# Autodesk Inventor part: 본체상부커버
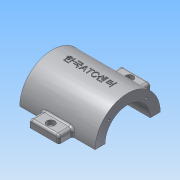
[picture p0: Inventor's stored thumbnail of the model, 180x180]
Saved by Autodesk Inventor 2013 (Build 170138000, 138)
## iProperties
Created: 2015-12
Part Number: 본체상부커버
Material: 알루미늄 6061
Document SubType Name: Modeling
Designer: mduedu
Density: 2.71 g/cm^3
Mass: 190.123 g
Surface Area: 187.8 cm^2
Volume: 70.1561 cm^3
Author: mduedu
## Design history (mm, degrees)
sketch "스케치1"
  geometry: L1 (45, 40)-(-45, 40); L2 (-45, 40)-(-45, -40); L3 (-45, -40)-(45, -40); L4 (45, -40)-(45, 40); L5 (45, 40)-(-45, -40); L6 (-45, 40)-(45, -40); 2 further points
  constraints: 12 end point, 2 midpoint, 2 parallel, 1 coincident, 1 horizontal, 1 perpendicular, 3 other
  dimensions: "d0" = 90 distance of L2.end L3.end; "d2" = 80 distance of L1.end L2.end
extrude "돌출1" new body sketch "스케치1" distance "d3" = 10; taper "d4" = 0 deg
sketch "스케치2"
  geometry: C1 r 32.5 at (80, 0); 1 further point
  constraints: 1 centre point
  dimensions: "d5" = 65 diameter of C1; "d116" = 80 distance of point (0, 0) C1.centre
extrude "돌출2" join sketch "스케치2" stored distance "d7" = 75; taper "d8" = 0 deg
sketch "스케치3"
  geometry: L1 (-27.5, -20)-(27.5, -20); L2 (27.5, -20)-(27.5, 20); L3 (27.5, 20)-(-27.5, 20); L4 (-27.5, 20)-(-27.5, -20); L5 (-27.5, -20)-(27.5, 20); L6 (27.5, -20)-(-27.5, 20); 1 further point
  constraints: 12 end point, 2 midpoint, 2 parallel, 1 horizontal, 1 perpendicular
  dimensions: "d9" = 55 distance of L2.end L3.end; "d11" = 40 distance of L1.end L2.end
extrude "돌출3" new body sketch "스케치3" stored distance "d12" = 75; taper "d13" = 0 deg
fillet "모깎기1"
fillet "모깎기2"
feature "결합1"
  node "솔리드2"
sketch "스케치4"
  geometry: L1 (-37.5, 47.5)-(37.5, 47.5) reference; L2 (32.5, 47.5)-(40.208, 10); L3 (37.5, 47.5)-(37.5, 112.5) reference; L4 (60.208, 0)-(60.208, 10) reference; L5 (60.208, 10)-(-60.208, 10) reference; 1 further point
  constraints: 2 end point, 2 point on line
  dimensions: "d15" = 5 distance from line of L2.start L3; "d117" = 20 distance from line of L2.end L4
sketch "스케치5"
  geometry: L1 (10, 35.208)-(56.729, 22.687); L2 (0, 60.208)-(10, 60.208) reference; L3 (10, -60.208)-(10, 60.208) reference; 2 further points
  constraints: 2 end point, 1 point on line, 2 other
  dimensions: "d118" = 25 distance from line of L1.start L2; "d119" = 75 deg angle of L1 L3
feature "리브1" dims "d19" = 1, "d20" = 6, "d21" = 0, "d22" = 0, "d23" = 1, "d24" = 1
feature "리브2" dims "d25" = 1, "d26" = 6, "d27" = 0, "d28" = 0, "d29" = 1, "d30" = 1
fillet "모깎기4" dims "d31" = 2
fillet "모깎기5" dims "d32" = 2
fillet "모깎기6" dims "d33" = 2
sketch "스케치6"
  geometry: L1 (0, 0)-(-32.88, 32.88); L2 (0, 0)-(-46.5, 0); A1 r 46.5 centre (0, 0) between (-32.88, 32.88) and (-46.5, 0); 5 further points
  constraints: 4 end point, 2 coincident, 2 point on circle, 1 centre point, 1 horizontal, 5 other
  dimensions: "d120" = 93 diameter of A1; "d122" = 45 deg angle of L1 L2; "d126" = 360 deg dimension on point (0, 0) point (-32.88, 32.88) (derived)
hole "구멍1" sketch "스케치6" at (-32.88, 32.88), (-32.88, -32.88), (32.88, -32.88), (32.88, 32.88) diameter "d34" = 7; stored, may be unused: countersink angle "d38" = 90 deg, drill point angle "d40" = 118 deg; dims "d35" = 6, "d36" = 12, "d37" = 3, "d39" = 8
fillet "모깎기13" dims "d131" = 3
hole "구멍2" diameter "d44" = 45; stored, may be unused: countersink angle "d48" = 90 deg, drill point angle "d50" = 118 deg; dims "d42" = 10, "d43" = 10, "d45" = 6, "d46" = 4, "d47" = 2, "d49" = 8
sketch "스케치7" dims "d52" = 26.5
  geometry: L1 (0, 0)-(32.5, 0); L2 (0, 0)-(22.981, 22.981); A1 r 32.5 centre (0, 0) between (32.5, 0) and (22.981, 22.981) reference; 3 further points
  constraints: 4 end point, 2 point on circle, 1 coincident, 1 horizontal, 1 point on line, 3 other
  dimensions: "d51" = 45 deg angle of L2 L1
hole "구멍3" sketch "스케치7" at (18.738, 18.738) diameter "d54" = 2.459; stored, may be unused: countersink angle "d58" = 90 deg, drill point angle "d60" = 118 deg; dims "d55" = 8, "d56" = 4, "d57" = 2, "d59" = 10
sketch "스케치8"
  geometry: L1 (72.5, 31.623)-(72.5, 46); L2 (72.5, 46)-(87.5, 46); L3 (87.5, 46)-(87.5, 31.623); A1 r 32.5 centre (80, 0) between (87.5, 31.623) and (72.5, 31.623) reference; 2 further points
  constraints: 6 end point, 2 point on circle, 1 horizontal, 1 midpoint, 1 parallel, 1 vertical, 1 vertical alignment
  dimensions: "d64" = 15 distance of L1.end L2.end; "d66" = 46 distance from line of L2 A1.centre
extrude "돌출4" join sketch "스케치8" stored distance "d67" = 30; taper "d68" = 0 deg
fillet "모깎기8" dims "d69" = 3
fillet "모깎기9" dims "d70" = 2
node "작업 평면2"
sketch "스케치16"
  geometry: L1 (33.166, 72.5)-(44, 72.5) reference; L2 (42.5, 72.5)-(28.53, 64.434); L3 (46, 75.5)-(46, 84.5) reference; 2 further points
  constraints: 2 end point, 1 point on line, 2 other
  dimensions: "d138" = 30 deg angle of L2 L1; "d139" = 3.5 distance from line of L2.start L3
feature "리브3" sketch "스케치16" dims "d140" = 1, "d141" = 3, "d142" = 0, "d143" = 0, "d144" = 1, "d145" = 1
fillet "모깎기14" dims "d146" = 1
fillet "모깎기15" dims "d147" = 1
sketch "스케치9"
  geometry: L1 (-76, -110)-(76, -110); L2 (76, -110)-(76, 0); L3 (76, 0)-(-76, 0); L4 (-76, 0)-(-76, -110); L5 (-46, 4.5)-(-46, -4.5) reference; L6 (-60.208, -80)-(60.208, -80) reference; C1 r 32.5 at (0, 0) reference; 2 further points
  constraints: 8 end point, 2 parallel, 1 coincident, 1 horizontal, 1 midpoint, 1 perpendicular
  dimensions: "d72" = 30 distance between parallel lines of L4 L5; "d148" = 30 distance between parallel lines of L6 L1
extrude "돌출5" cut sketch "스케치9" stored distance "d73" = 0; taper "d74" = 0 deg
node "작업 평면3"
sketch "스케치17"
  geometry: 2 further points
  constraints: 1 coincident, 1 other
feature "엠보싱1" sketch "스케치17" dims "d12" = 75, "d13" = 0, "d150" = 0.5, "d151" = 0
sketch "스케치18"
  geometry: L1 (-3, -1.039)-(-3, -10.834) reference; L2 (27, -10.834)-(27, -1.039) reference; L3 (0, -12.834)-(24, -12.834) reference; L4 (-3, -5.936)-(27, -5.936); L5 (12, -12.834)-(12, 33.166); 1 further point
  constraints: 4 end point, 4 midpoint, 1 perpendicular, 1 point on line
hole "구멍8" sketch "스케치18" at (12, -5.936) diameter "d152" = 4.5; stored, may be unused: countersink angle "d156" = 90 deg, drill point angle "d158" = 118 deg; dims "d153" = 6, "d154" = 8, "d155" = 4.6, "d157" = 8
node "솔리드1"
mirror "대칭1"
mirror "대칭2"
pattern_circular "원형 패턴1" dims angle "d62" = 360 deg
mirror "대칭3"
mirror "대칭7"
mirror "대칭4"
mirror "대칭8"
other parameters: "d137" = -5
